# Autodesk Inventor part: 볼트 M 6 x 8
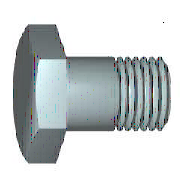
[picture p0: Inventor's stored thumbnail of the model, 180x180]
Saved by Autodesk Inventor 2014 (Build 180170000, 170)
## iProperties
Created: 2012-02
Part Number: 볼트 M 6 x 8
Material: 강철, 연강
Description: 6각 머리 볼트 및 6각 머리 나사
Document SubType Name: Modeling
Standard: KS B 1002
Designer: mduedu
Standards Organization: KS
Language: ko-KR
Size Designation: C  M 6 x 12
Categories: <MemberInstance><Categories><Category DisplayName="조임쇠" InternalName="e4da775c-781d-43d5-af7c-5136215cf5a6" Mnemonic="FSTN"><Category DisplayName="볼트" InternalN
Density: 1 g/cm^3
Appearance: 강철
IsCustomPart: 1
Author: mduedu
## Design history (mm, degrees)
sketch "스케치1"
  geometry: L1 (0, 3)-(8, 3); L2 (8, 3)-(8, 0); L3 (8, 0)-(0, 0); L4 (-2.4, 0)-(14.4, 0) reference; L5 (0, -0.6)-(0, 3.6) reference; L6 (0, 3)-(0, 0)
  constraints: 8 end point, 3 point on line, 1 collinear
  dimensions: "d2" = 6 diameter of L1 L3 (= GD); "d59" = 8 distance between parallel lines of L2 L5 (= NLG)
revolve "본체" sketch "스케치1" stored, may be unused: angle "d12" = 90 deg
sketch "스케치2"
  geometry: L1 (0, 5.774)-(5, 2.887); L2 (5, 2.887)-(5, -2.887); L3 (5, -2.887)-(0, -5.774); L4 (0, -5.774)-(-5, -2.887); L5 (-5, -2.887)-(-5, 2.887); L6 (-5, 2.887)-(0, 5.774); L7 (-7, 0)-(7, 0) reference; L8 (0, 8.083)-(0, -8.083) reference; 2 further points
  constraints: 12 end point, 2 midpoint, 1 coincident, 1 vertical, 11 other
  dimensions: "d11" = 10 distance between parallel lines of L5 L2 (= SW)
extrude "머리" join sketch "스케치2" distance "d3" = 4 (= KOH); taper "d4" = 0 deg
revolve "모따기1" stored, may be unused: angle "d21" = 90 deg
workplane "Work Plane1"
body "Solid1"
feature "스레드" dims "d15" = 9 (= GEL), "d16" = 0
chamfer "모따기2" distance "d6" = 0.61345 (= -0.5 x SPD + 0.5 x GD); stored, may be unused: second distance "d7" = 0.61355 (computed from GUL), angle "d55" = 45 deg
sketch "스케치4"
  geometry: L1 (-3.423, 6)-(-4, 5); L2 (-1.1, 0)-(-0.234, 0); L3 (-4.753, 0)-(0.519, 0) reference; L4 (-4, 6)-(-3.423, 6); L5 (-4, 5)-(-4, 6); L6 (0, 7.2)-(0, -1.2) reference
  constraints: 8 end point, 1 parallel, 1 perpendicular, 1 point on line
  dimensions: "d65" = 10 diameter of L1.end L2 (= SW); "d67" = 30 deg angle of L1 L5 (= ANG1); "d68" = 12 diameter of L4 L2 (= 1.2 x SW); "d69" = 4 distance between parallel lines of L5 L6 (= KOH)
other parameters: "NLG" = 8 [user parameter; used in 1 equation term], "GD" = 6 (= NND) [user parameter; used in 2 equation terms], "BDM" = 6 (= NND) [user parameter], "KOH" = 4 [user parameter; used in 2 equation terms], "GEL" = 9 [user parameter; used in 1 equation term], "SW" = 10 [user parameter; used in 5 equation terms], "SPD" = 4.7731 (= NND - 1.2269 x PTC) [user parameter; used in 1 equation term], "SD2" = 6 (= NND) [user parameter], "SD" = 0 [user parameter], "ANG1" = 30 deg [user parameter; used in 1 equation term], "GAL" = 0.61345 (= 0.61345 x PTC) [user parameter], "GUL" = 0.61345 (= 0.61345 x PTC) [user parameter; used in 1 equation term], "d8" = 0, "RR" = 0.25 [user parameter], "d58" = 0, "RR1" = 0.1 [user parameter], "GD1" = 4.7731 (= THREADDIA - 1.2269 x PTC) [user parameter], "THREADDIA" = 6 [user parameter; used in 1 equation term], "TOA" = 30 deg [user parameter], "PTC" = 1 [user parameter; used in 5 equation terms], "NND" = 6 [user parameter; used in 4 equation terms], "E0" = 11.55 (= 1.155 x SW) [user parameter]
